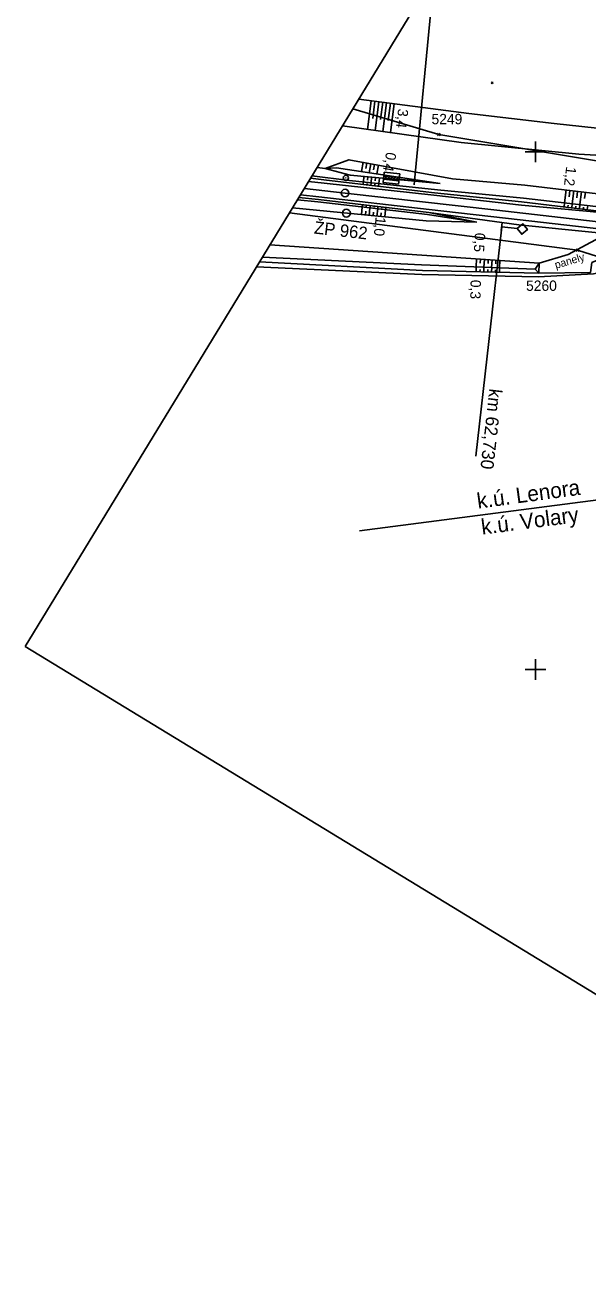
# Model space of a CAD drawing. Extents: x -804899 to -803847, y -1165742 to -1164942.
# Drawn here: x -804898.6 to -804789.9, y -1165320 to -1165075.5 of the extents above; entities that cross this region are included whole.
import ezdxf

# ---------------------------------------------------------------- set-up
doc = ezdxf.new("R2010")
doc.units = 0
for name, color, linetype in [('0381KM061-064P - Vrstva 1', 7, 'Continuous'), ('0381KM061-064P - Vrstva 16', 7, 'Continuous'), ('0381KM061-064P - Vrstva 4', 7, 'Continuous'), ('0381KM061-064P - Vrstva 48', 7, 'Continuous'), ('0381KM061-064P - Vrstva 49', 7, 'Continuous'), ('0381KM061-064P - Vrstva 51', 7, 'Continuous'), ('0381KM061-064P - Vrstva 55', 7, 'Continuous'), ('0381KM061-064P - Vrstva 7', 7, 'Continuous'), ('0381KM061-064P - Vrstva 8', 7, 'Continuous'), ('formát', 7, 'Continuous'), ('krizky_1000 - Vrstva 1', 7, 'Continuous'), ('szdc - hran DP', 7, 'Continuous'), ('szdc - szdc_cislo', 7, 'Continuous'), ('szdc - szdc_krizek', 7, 'Continuous'), ('vyt_sit - stávající', 7, 'Continuous')]:
    doc.layers.add(name, color=color, linetype=linetype)

msp = doc.modelspace()

# ---------------------------------------------------------------- linework, layer by layer
at = {"layer": '0381KM061-064P - Vrstva 1'}
msp.add_lwpolyline([(-804844.65, -1165107.07), (-804836.78, -1165107.96), (-804807.43, -1165111.28), (-804784.52, -1165113.87), (-804783.45, -1165113.99)], dxfattribs=at)
at = {"layer": '0381KM061-064P - Vrstva 16'}
msp.add_lwpolyline([(-804799.35, -1165123.41), (-804799.3, -1165121.51), (-804793.65, -1165119.83), (-804787.56, -1165116.52), (-804784.63, -1165116.88), (-804783.05, -1165118.1), (-804783.21, -1165118.97), (-804789.08, -1165121.4), (-804789.37, -1165123.31), (-804799.35, -1165123.41)], dxfattribs=at)
at = {"layer": '0381KM061-064P - Vrstva 4'}
for points in [[(-804843.83, -1165105.73), (-804840.8, -1165106.06), (-804819.65, -1165108.38), (-804802.7, -1165110.3), (-804779.71, -1165112.39), (-804771.59, -1165113.78)], [(-804843.45, -1165105.1), (-804840.34, -1165105.46), (-804819.52, -1165107.92), (-804802.69, -1165109.64), (-804779.71, -1165112.39)], [(-804845.7, -1165108.79), (-804841.9, -1165109.22), (-804820.58, -1165111.74), (-804803.21, -1165114.08), (-804774.36, -1165117.01), (-804771.98, -1165116.64)], [(-804845.41, -1165108.32), (-804841.86, -1165108.69), (-804820.53, -1165111.13), (-804802.92, -1165113.13), (-804771.98, -1165116.64)]]:
    msp.add_lwpolyline(points, dxfattribs=at)
at = {"layer": '0381KM061-064P - Vrstva 48'}
for p, q in [((-804832.45, -1165095.65), (-804831.74, -1165090.13)), ((-804831.42, -1165093.54), (-804831, -1165090.23)), ((-804830.97, -1165095.86), (-804830.25, -1165090.32)), ((-804829.94, -1165093.74), (-804829.51, -1165090.42)), ((-804829.48, -1165096.06), (-804828.77, -1165090.52)), ((-804828.45, -1165093.95), (-804828.02, -1165090.61)), ((-804827.99, -1165096.27), (-804827.28, -1165090.71)), ((-804833.61, -1165103.81), (-804833.29, -1165102.02)), ((-804832.74, -1165103.22), (-804832.55, -1165102.15)), ((-804832.13, -1165104.04), (-804831.81, -1165102.29)), ((-804831.26, -1165103.46), (-804831.07, -1165102.42)), ((-804830.65, -1165104.27), (-804830.33, -1165102.56)), ((-804833.23, -1165105.8), (-804833.29, -1165106.29)), ((-804833.24, -1165105.79), (-804833.15, -1165104.77)), ((-804832.51, -1165106.08), (-804832.54, -1165106.38)), ((-804832.46, -1165105.46), (-804832.4, -1165104.84)), ((-804831.74, -1165105.96), (-804831.8, -1165106.47)), ((-804831.75, -1165105.96), (-804831.66, -1165104.91)), ((-804831.02, -1165106.25), (-804831.05, -1165106.55)), ((-804830.97, -1165105.61), (-804830.91, -1165104.98)), ((-804830.25, -1165106.12), (-804830.31, -1165106.64)), ((-804830.26, -1165106.12), (-804830.16, -1165105.05)), ((-804794.08, -1165107.35), (-804794.37, -1165109.84)), ((-804793.33, -1165107.44), (-804793.48, -1165108.68)), ((-804792.59, -1165107.53), (-804792.88, -1165110.01)), ((-804791.84, -1165107.62), (-804791.99, -1165108.86)), ((-804791.1, -1165107.71), (-804791.39, -1165110.18)), ((-804790.35, -1165107.79), (-804790.5, -1165109.03)), ((-804833.61, -1165112.12), (-804833.46, -1165110.65)), ((-804833.4, -1165110.23), (-804833.45, -1165110.65)), ((-804832.86, -1165112.2), (-804832.79, -1165111.47)), ((-804832.66, -1165110.31), (-804832.68, -1165110.53)), ((-804832.11, -1165112.27), (-804831.97, -1165110.82)), ((-804831.91, -1165110.4), (-804831.96, -1165110.82)), ((-804831.17, -1165110.49), (-804831.19, -1165110.7)), ((-804830.62, -1165112.41), (-804830.48, -1165111)), ((-804830.42, -1165110.58), (-804830.47, -1165111)), ((-804829.68, -1165110.67), (-804829.7, -1165110.87)), ((-804829.13, -1165112.56), (-804828.99, -1165111.17)), ((-804828.93, -1165110.75), (-804828.98, -1165111.17)), ((-804794.47, -1165110.62), (-804794.37, -1165109.84)), ((-804793.72, -1165110.71), (-804793.67, -1165110.32)), ((-804792.98, -1165110.8), (-804792.88, -1165110.01)), ((-804792.23, -1165110.89), (-804792.18, -1165110.49)), ((-804791.49, -1165110.98), (-804791.39, -1165110.18)), ((-804790.74, -1165111.07), (-804790.69, -1165110.67)), ((-804790, -1165111.16), (-804789.9, -1165110.35)), ((-804831.37, -1165112.34), (-804831.3, -1165111.62)), ((-804829.87, -1165112.48), (-804829.81, -1165111.78)), ((-804811.36, -1165120.67), (-804811.46, -1165122.21)), ((-804810.61, -1165120.72), (-804810.66, -1165121.48)), ((-804809.86, -1165120.78), (-804809.96, -1165122.27)), ((-804809.11, -1165120.83), (-804809.16, -1165121.56)), ((-804808.36, -1165120.88), (-804808.46, -1165122.33)), ((-804807.62, -1165120.93), (-804807.67, -1165121.65)), ((-804806.87, -1165120.98), (-804806.97, -1165122.39)), ((-804811.47, -1165123.14), (-804811.45, -1165122.21)), ((-804810.72, -1165123.15), (-804810.71, -1165122.7)), ((-804809.97, -1165123.17), (-804809.95, -1165122.27)), ((-804809.22, -1165123.19), (-804809.21, -1165122.74)), ((-804808.47, -1165123.2), (-804808.45, -1165122.33)), ((-804807.72, -1165123.22), (-804807.71, -1165122.79)), ((-804806.97, -1165123.24), (-804806.95, -1165122.39))]:
    msp.add_line(p, q, dxfattribs=at)
at = {"layer": '0381KM061-064P - Vrstva 49'}
for p, q in [((-804808.18, -1165086.83), (-804808.54, -1165086.48)), ((-804808.18, -1165086.48), (-804808.54, -1165086.83))]:
    msp.add_line(p, q, dxfattribs=at)
for points in [[(-804834.14, -1165089.82), (-804812.85, -1165092.56), (-804796.39, -1165094.52), (-804782.73, -1165096.03), (-804774.67, -1165096.28), (-804769.92, -1165095.77)], [(-804837.28, -1165094.97), (-804814.35, -1165098.18)], [(-804814.35, -1165098.18), (-804791.62, -1165100.43), (-804782.93, -1165100.95)], [(-804840.64, -1165103.22), (-804836.05, -1165101.51), (-804816.03, -1165105.18), (-804802.02, -1165106.41), (-804778.12, -1165109.25)], [(-804842.2, -1165103.05), (-804840.64, -1165103.22)], [(-804840.64, -1165103.22), (-804838.47, -1165103.07), (-804818.4, -1165106.14)], [(-804840.64, -1165103.22), (-804835.82, -1165104.53), (-804840.64, -1165103.22), (-804835.82, -1165104.53), (-804818.4, -1165106.14)], [(-804843.45, -1165105.1), (-804840.34, -1165105.46), (-804819.52, -1165107.92), (-804802.69, -1165109.64), (-804779.71, -1165112.39)], [(-804843.18, -1165104.66), (-804835.93, -1165105.5), (-804818.93, -1165107.36), (-804802.32, -1165108.93), (-804779.97, -1165111.49)], [(-804845.7, -1165108.79), (-804841.9, -1165109.22), (-804820.58, -1165111.74), (-804811.31, -1165113.56)], [(-804846.95, -1165110.84), (-804821.13, -1165113.33), (-804811.31, -1165113.56)], [(-804845.98, -1165109.25), (-804842.05, -1165109.66), (-804820.85, -1165112.11), (-804811.31, -1165113.56)], [(-804851.29, -1165117.97), (-804821.94, -1165119.94), (-804799.3, -1165121.51)], [(-804853.31, -1165121.27), (-804821.85, -1165122.9), (-804799.35, -1165123.41)], [(-804852.74, -1165120.35), (-804821.99, -1165121.8), (-804800.02, -1165122.66)], [(-804799.3, -1165121.51), (-804800.02, -1165122.66), (-804799.35, -1165123.41)]]:
    msp.add_lwpolyline(points, dxfattribs=at)
at = {"layer": '0381KM061-064P - Vrstva 51'}
for points in [[(-804799.4, -1165124.13), (-804788.79, -1165123.56), (-804781.18, -1165122.08), (-804777.38, -1165120.68), (-804772.77, -1165118.03), (-804766.25, -1165113.72), (-804759.19, -1165108.08), (-804752.39, -1165104.15), (-804745.74, -1165101.09), (-804737.37, -1165099.16), (-804728.56, -1165098.53)], [(-804853.87, -1165122.19), (-804821.92, -1165123.67), (-804799.4, -1165124.13)]]:
    msp.add_lwpolyline(points, dxfattribs=at)
at = {"layer": '0381KM061-064P - Vrstva 55'}
msp.add_lwpolyline([(-804834.02, -1165173.21), (-804777.95, -1165165.95), (-804761.65, -1165133.49), (-804755.48, -1165121.19), (-804751.26, -1165114.04), (-804741.92, -1165100.8), (-804736.13, -1165096.49), (-804701.79, -1165069.72), (-804628.3, -1165012.44)], dxfattribs=at)
at = {"layer": '0381KM061-064P - Vrstva 7'}
msp.add_line((-804836.67, -1165105.01), (-804836.57, -1165105.03), dxfattribs=at)
for centre, radius in [((-804836.62, -1165105.02), 0.5), ((-804836.78, -1165107.96), 0.75)]:
    msp.add_circle(centre, radius, dxfattribs=at)
at = {"layer": '0381KM061-064P - Vrstva 8'}
for p, q in [((-804823.36, -1165105.59), (-804819.58, -1165065.95)), ((-804829.06, -1165104.6), (-804829.31, -1165104.79)), ((-804828.53, -1165104.66), (-804829.3, -1165105.27)), ((-804828.01, -1165104.72), (-804828.78, -1165105.33)), ((-804827.48, -1165104.77), (-804828.25, -1165105.39)), ((-804826.95, -1165104.83), (-804827.72, -1165105.45)), ((-804826.42, -1165104.89), (-804827.2, -1165105.51)), ((-804826.35, -1165105.31), (-804826.67, -1165105.57)), ((-804823.44, -1165106.34), (-804823.28, -1165104.85)), ((-804806.43, -1165113.71), (-804806.59, -1165115.21)), ((-804806.51, -1165114.46), (-804811.49, -1165158.76))]:
    msp.add_line(p, q, dxfattribs=at)
for points in [[(-804826.45, -1165106.25), (-804829.43, -1165105.91), (-804829.21, -1165103.92), (-804826.23, -1165104.26), (-804826.45, -1165106.25)], [(-804826.34, -1165105.26), (-804823.36, -1165105.59)], [(-804806.51, -1165114.46), (-804803.53, -1165114.8), (-804802.42, -1165113.91), (-804801.54, -1165115.02), (-804802.65, -1165115.9), (-804803.53, -1165114.8)]]:
    msp.add_lwpolyline(points, dxfattribs=at)
msp.add_lwpolyline([(-804826.38, -1165105.6), (-804829.36, -1165105.26), (-804829.28, -1165104.57), (-804826.3, -1165104.91)], close=True, dxfattribs=at)
at = {"layer": 'formát'}
for p in [(-804743.98, -1164941.92), (-804360.64, -1165523.44)]:
    msp.add_line(p, (-804898.57, -1165195.52), dxfattribs=at)
at = {"layer": 'krizky_1000 - Vrstva 1'}
for points in [[(-804800, -1165098), (-804800, -1165102)], [(-804802, -1165100), (-804798, -1165100)], [(-804800, -1165198), (-804800, -1165202)], [(-804802, -1165200), (-804798, -1165200)]]:
    msp.add_lwpolyline(points, dxfattribs=at)
at = {"layer": 'szdc - hran DP'}
for p, q in [((-804835.27, -1165091.67), (-804818.68, -1165096.66)), ((-804818.68, -1165096.66), (-804777.08, -1165103.56)), ((-804791.88, -1165118.97), (-804847.53, -1165111.8)), ((-804781.51, -1165122.32), (-804791.88, -1165118.97))]:
    msp.add_line(p, q, dxfattribs=at)
at = {"layer": 'szdc - szdc_krizek'}
for p, q in [((-804818.42, -1165096.93), (-804818.95, -1165096.4)), ((-804818.95, -1165096.93), (-804818.42, -1165096.4)), ((-804791.61, -1165119.24), (-804792.15, -1165118.71)), ((-804792.15, -1165119.24), (-804791.61, -1165118.71))]:
    msp.add_line(p, q, dxfattribs=at)
at = {"layer": 'vyt_sit - stávající'}
msp.add_line((-804836.57, -1165111.8), (-804836.48, -1165111.85), dxfattribs=at)
msp.add_circle((-804836.52, -1165111.83), 0.756, dxfattribs=at)

# ---------------------------------------------------------------- texts
at = {"layer": '0381KM061-064P - Vrstva 16'}
msp.add_text('panely', height=1.5, rotation=16.5596, dxfattribs=at).set_placement((-804796.03, -1165122.6))
at = {"layer": '0381KM061-064P - Vrstva 48'}
for s, rotation, p in [('3,4', 262.6656, (-804826.51, -1165091.58)), ('0,4', 259.6289, (-804828.81, -1165099.95)), ('1,2', 263.2123, (-804794.05, -1165102.78)), ('1,0', 264.4873, (-804830.87, -1165112.47)), ('0,5', 266.024, (-804811.67, -1165115.58)), ('0,3', 268.6994, (-804812.52, -1165124.7))]:
    msp.add_text(s, height=2, rotation=rotation, dxfattribs=at).set_placement(p)
at = {"layer": '0381KM061-064P - Vrstva 55'}
for s, rotation, p in [('k.ú. Lenora', 7.7713, (-804811.1, -1165168.94)), ('k.ú. Volary', 7.4655, (-804810.29, -1165173.96))]:
    msp.add_text(s, height=3, rotation=rotation, dxfattribs=at).set_placement(p)
at = {"layer": '0381KM061-064P - Vrstva 8'}
msp.add_text('km 62,730', height=2.5, rotation=263.5832, dxfattribs=at).set_placement((-804808.89, -1165145.66))
at = {"layer": 'szdc - szdc_cislo'}
for s, p in [('5249', (-804820.08, -1165094.66)), ('5260', (-804801.81, -1165126.85))]:
    msp.add_text(s, height=2, dxfattribs=at).set_placement(p)
at = {"layer": 'vyt_sit - stávající'}
msp.add_text('ŽP 962', height=2.4, rotation=353.5611, dxfattribs=at).set_placement((-804842.86, -1165115.77))

doc.saveas('drawing.dxf')
